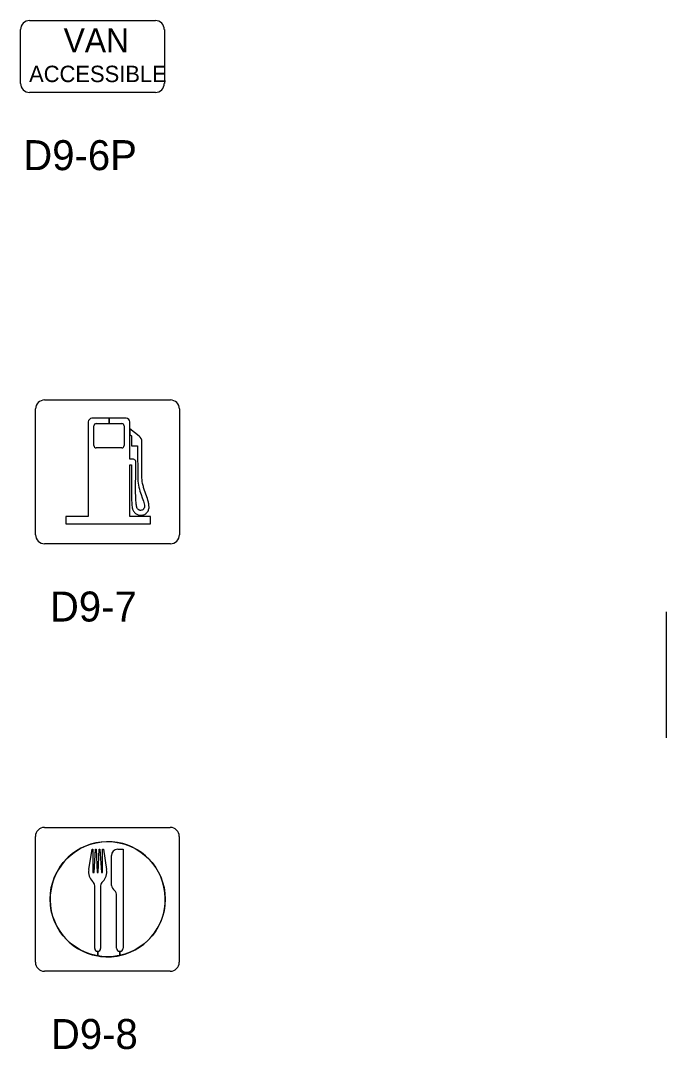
# Model space of a CAD drawing. Extents: x 42133 to 45533, y 41351 to 47951.
# Drawn here: x 42524.5 to 42686.1, y 47420.5 to 47677.8 of the extents above; entities that cross this region are included whole.
import ezdxf

# ---------------------------------------------------------------- set-up
doc = ezdxf.new("R2010")
doc.units = 0
doc.layers.add('P_TRAF_SIGN_SignDetails', color=7, linetype='Continuous')

msp = doc.modelspace()

# ---------------------------------------------------------------- linework, layer by layer
at = {"layer": 'P_TRAF_SIGN_SignDetails'}
for p, q in [((42526.75, 47677.76), (42558.23, 47677.76)), ((42524.5, 47662.03), (42524.5, 47675.51)), ((42560.48, 47675.51), (42560.48, 47662.03)), ((42558.23, 47659.79), (42526.75, 47659.79)), ((42530.52, 47582.89), (42562, 47582.89)), ((42528.26, 47549.15), (42528.26, 47580.64)), ((42564.24, 47580.64), (42564.24, 47549.15)), ((42562, 47546.91), (42530.52, 47546.91)), ((42686.09, 47498.42), (42686.09, 47529.91)), ((42530.48, 47475.99), (42561.96, 47475.99)), ((42528.23, 47442.25), (42528.23, 47473.74)), ((42564.21, 47473.74), (42564.21, 47442.25)), ((42561.96, 47440.01), (42530.48, 47440.01))]:
    msp.add_line(p, q, dxfattribs=at)
for points in [[(42541.44, 47577.37), (42541.44, 47553.76), (42535.82, 47553.76), (42535.82, 47551.9), (42557, 47551.9), (42557, 47553.76), (42551.86, 47553.76), (42551.86, 47566.63), (42552.28, 47566.63), (42552.26, 47564.41), (42552.24, 47562.81), (42552.24, 47561.08), (42552.24, 47560.21), (42552.25, 47559.36), (42552.26, 47558.55), (42552.28, 47557.8), (42552.32, 47557.12), (42552.36, 47556.53), (42552.42, 47556.05), (42552.45, 47555.86), (42552.48, 47555.71), (42552.54, 47555.53), (42552.61, 47555.37), (42552.69, 47555.2), (42552.79, 47555.05), (42552.89, 47554.91), (42553.01, 47554.76), (42553.27, 47554.52), (42553.42, 47554.41), (42553.57, 47554.31), (42553.73, 47554.23), (42553.89, 47554.16), (42554.06, 47554.1), (42554.23, 47554.06), (42554.4, 47554.03), (42554.59, 47554.03), (42554.79, 47554.03), (42554.99, 47554.07), (42555.19, 47554.12), (42555.38, 47554.19), (42555.56, 47554.27), (42555.73, 47554.38), (42555.81, 47554.43), (42555.89, 47554.5), (42556.04, 47554.63), (42556.17, 47554.78), (42556.29, 47554.94), (42556.4, 47555.11), (42556.48, 47555.29), (42556.55, 47555.48), (42556.6, 47555.68), (42556.64, 47555.88), (42556.64, 47556.09), (42556.62, 47556.51), (42556.57, 47556.94), (42556.53, 47557.15), (42556.48, 47557.36), (42556.37, 47557.8), (42556.23, 47558.23), (42556.09, 47558.67), (42555.76, 47559.56), (42555.44, 47560.49), (42555.29, 47560.98), (42555.22, 47561.22), (42555.15, 47561.47), (42555.04, 47561.98), (42554.95, 47562.49), (42554.9, 47563.03), (42554.88, 47563.3), (42554.88, 47563.58), (42554.88, 47572.47)], [(42541.44, 47577.37), (42541.44, 47553.76), (42535.82, 47553.76), (42535.82, 47551.9), (42557, 47551.9), (42557, 47553.76), (42551.86, 47553.76), (42551.86, 47566.63), (42552.28, 47566.63), (42552.26, 47564.41), (42552.24, 47562.81), (42552.24, 47561.08), (42552.24, 47560.21), (42552.25, 47559.36), (42552.26, 47558.55), (42552.28, 47557.8), (42552.32, 47557.12), (42552.36, 47556.53), (42552.42, 47556.05), (42552.45, 47555.86), (42552.48, 47555.71), (42552.54, 47555.53), (42552.61, 47555.37), (42552.69, 47555.2), (42552.79, 47555.05), (42552.89, 47554.91), (42553.01, 47554.76), (42553.27, 47554.52), (42553.42, 47554.41), (42553.57, 47554.31), (42553.73, 47554.23), (42553.89, 47554.16), (42554.06, 47554.1), (42554.23, 47554.06), (42554.4, 47554.03), (42554.59, 47554.03), (42554.79, 47554.03), (42554.99, 47554.07), (42555.19, 47554.12), (42555.38, 47554.19), (42555.56, 47554.27), (42555.73, 47554.38), (42555.81, 47554.43), (42555.89, 47554.5), (42556.04, 47554.63), (42556.17, 47554.78), (42556.29, 47554.94), (42556.4, 47555.11), (42556.48, 47555.29), (42556.55, 47555.48), (42556.6, 47555.68), (42556.64, 47555.88), (42556.64, 47556.09), (42556.62, 47556.51), (42556.57, 47556.94), (42556.53, 47557.15), (42556.48, 47557.36), (42556.37, 47557.8), (42556.23, 47558.23), (42556.09, 47558.67), (42555.76, 47559.56), (42555.44, 47560.49), (42555.29, 47560.98), (42555.22, 47561.22), (42555.15, 47561.47), (42555.04, 47561.98), (42554.95, 47562.49), (42554.9, 47563.03), (42554.88, 47563.3), (42554.88, 47563.58), (42554.88, 47572.47)], [(42541.44, 47577.37), (42541.44, 47553.76), (42535.82, 47553.76), (42535.82, 47551.9), (42557, 47551.9), (42557, 47553.76), (42551.86, 47553.76), (42551.86, 47566.63), (42552.28, 47566.63), (42552.26, 47564.41), (42552.24, 47562.81), (42552.24, 47561.08), (42552.24, 47560.21), (42552.25, 47559.36), (42552.26, 47558.55), (42552.28, 47557.8), (42552.32, 47557.12), (42552.36, 47556.53), (42552.42, 47556.05), (42552.45, 47555.86), (42552.48, 47555.71), (42552.54, 47555.53), (42552.61, 47555.37), (42552.69, 47555.2), (42552.79, 47555.05), (42552.89, 47554.91), (42553.01, 47554.76), (42553.27, 47554.52), (42553.42, 47554.41), (42553.57, 47554.31), (42553.73, 47554.23), (42553.89, 47554.16), (42554.06, 47554.1), (42554.23, 47554.06), (42554.4, 47554.03), (42554.59, 47554.03), (42554.79, 47554.03), (42554.99, 47554.07), (42555.19, 47554.12), (42555.38, 47554.19), (42555.56, 47554.27), (42555.73, 47554.38), (42555.81, 47554.43), (42555.89, 47554.5), (42556.04, 47554.63), (42556.17, 47554.78), (42556.29, 47554.94), (42556.4, 47555.11), (42556.48, 47555.29), (42556.55, 47555.48), (42556.6, 47555.68), (42556.64, 47555.88), (42556.64, 47556.09), (42556.62, 47556.51), (42556.57, 47556.94), (42556.53, 47557.15), (42556.48, 47557.36), (42556.37, 47557.8), (42556.23, 47558.23), (42556.09, 47558.67), (42555.76, 47559.56), (42555.44, 47560.49), (42555.29, 47560.98), (42555.22, 47561.22), (42555.15, 47561.47), (42555.04, 47561.98), (42554.95, 47562.49), (42554.9, 47563.03), (42554.88, 47563.3), (42554.88, 47563.58), (42554.88, 47572.47)], [(42550.93, 47578.3), (42542.37, 47578.3)], [(42543.45, 47576.96), (42546.65, 47576.96), (42546.65, 47578.3), (42542.37, 47578.3)], [(42543.45, 47576.96), (42546.65, 47576.96), (42546.65, 47578.3), (42542.37, 47578.3)], [(42542.85, 47571.49), (42542.85, 47576.37)], [(42542.85, 47571.49), (42542.85, 47576.37)], [(42542.85, 47571.49), (42542.85, 47576.37)], [(42543.45, 47576.96), (42549.83, 47576.96)], [(42550.93, 47578.3), (42546.65, 47578.3), (42546.65, 47576.96), (42549.83, 47576.96)], [(42550.93, 47578.3), (42546.65, 47578.3), (42546.65, 47576.96), (42549.83, 47576.96)], [(42550.42, 47576.37), (42550.42, 47571.49)], [(42550.42, 47576.37), (42550.42, 47571.49)], [(42550.42, 47576.37), (42550.42, 47571.49)], [(42554.15, 47573.82), (42551.86, 47575.7), (42551.86, 47577.37)], [(42554.15, 47573.82), (42551.86, 47575.7), (42551.86, 47574.23), (42552.28, 47573.91), (42552.28, 47571.45), (42553.78, 47571.45), (42553.85, 47563.07), (42553.85, 47562.82), (42553.87, 47562.56), (42553.92, 47562.05), (42554, 47561.55), (42554.11, 47561.06), (42554.22, 47560.58), (42554.36, 47560.11), (42554.66, 47559.21), (42554.96, 47558.37), (42555.1, 47557.97), (42555.22, 47557.59), (42555.33, 47557.22), (42555.41, 47556.88), (42555.47, 47556.55), (42555.49, 47556.39), (42555.5, 47556.24), (42555.48, 47556.04), (42555.43, 47555.86), (42555.39, 47555.78), (42555.34, 47555.7), (42555.28, 47555.62), (42555.22, 47555.55), (42555.15, 47555.49), (42555.08, 47555.44), (42554.91, 47555.35), (42554.82, 47555.31), (42554.73, 47555.29), (42554.53, 47555.27), (42554.42, 47555.27), (42554.31, 47555.29), (42554.2, 47555.33), (42554.08, 47555.38), (42553.97, 47555.46), (42553.86, 47555.55), (42553.76, 47555.66), (42553.67, 47555.79), (42553.61, 47555.92), (42553.56, 47556.08), (42553.51, 47556.29), (42553.47, 47556.54), (42553.43, 47556.81), (42553.4, 47557.13), (42553.35, 47557.84), (42553.31, 47558.65), (42553.3, 47559.08), (42553.29, 47559.53), (42553.28, 47560.46), (42553.28, 47561.41), (42553.29, 47562.38), (42553.3, 47563.31), (42553.33, 47565.05), (42553.36, 47566.42), (42553.37, 47567.28), (42553.36, 47567.43), (42553.31, 47567.58), (42553.24, 47567.72), (42553.14, 47567.83), (42553.03, 47567.93), (42552.9, 47568), (42552.75, 47568.05), (42552.59, 47568.06), (42551.86, 47568.09), (42551.86, 47577.37)], [(42554.15, 47573.82), (42551.86, 47575.7), (42551.86, 47574.23), (42552.28, 47573.91), (42552.28, 47571.45), (42553.78, 47571.45), (42553.85, 47563.07), (42553.85, 47562.82), (42553.87, 47562.56), (42553.92, 47562.05), (42554, 47561.55), (42554.11, 47561.06), (42554.22, 47560.58), (42554.36, 47560.11), (42554.66, 47559.21), (42554.96, 47558.37), (42555.1, 47557.97), (42555.22, 47557.59), (42555.33, 47557.22), (42555.41, 47556.88), (42555.47, 47556.55), (42555.49, 47556.39), (42555.5, 47556.24), (42555.48, 47556.04), (42555.43, 47555.86), (42555.39, 47555.78), (42555.34, 47555.7), (42555.28, 47555.62), (42555.22, 47555.55), (42555.15, 47555.49), (42555.08, 47555.44), (42554.91, 47555.35), (42554.82, 47555.31), (42554.73, 47555.29), (42554.53, 47555.27), (42554.42, 47555.27), (42554.31, 47555.29), (42554.2, 47555.33), (42554.08, 47555.38), (42553.97, 47555.46), (42553.86, 47555.55), (42553.76, 47555.66), (42553.67, 47555.79), (42553.61, 47555.92), (42553.56, 47556.08), (42553.51, 47556.29), (42553.47, 47556.54), (42553.43, 47556.81), (42553.4, 47557.13), (42553.35, 47557.84), (42553.31, 47558.65), (42553.3, 47559.08), (42553.29, 47559.53), (42553.28, 47560.46), (42553.28, 47561.41), (42553.29, 47562.38), (42553.3, 47563.31), (42553.33, 47565.05), (42553.36, 47566.42), (42553.37, 47567.28), (42553.36, 47567.43), (42553.31, 47567.58), (42553.24, 47567.72), (42553.14, 47567.83), (42553.03, 47567.93), (42552.9, 47568), (42552.75, 47568.05), (42552.59, 47568.06), (42551.86, 47568.09), (42551.86, 47577.37)], [(42549.83, 47570.89), (42543.45, 47570.89)], [(42549.83, 47570.89), (42543.45, 47570.89)], [(42549.83, 47570.89), (42543.45, 47570.89)], [(42541.57, 47465.42), (42542.39, 47470.51), (42542.57, 47470.51), (42542.57, 47464.75), (42542.88, 47464.75), (42543.27, 47470.51), (42543.4, 47470.51)], [(42541.57, 47465.42), (42542.39, 47470.51), (42542.57, 47470.51), (42542.57, 47464.75), (42542.88, 47464.75), (42543.27, 47470.51), (42543.4, 47470.51), (42543.65, 47464.75), (42543.94, 47464.75), (42544.2, 47470.51), (42544.32, 47470.51), (42544.72, 47464.75), (42545.03, 47464.75), (42545.03, 47470.51), (42545.21, 47470.51)], [(42541.57, 47465.42), (42542.39, 47470.51), (42542.57, 47470.51), (42542.57, 47464.75), (42542.88, 47464.75), (42543.27, 47470.51), (42543.4, 47470.51), (42543.65, 47464.75), (42543.94, 47464.75), (42544.2, 47470.51), (42544.32, 47470.51), (42544.72, 47464.75), (42545.03, 47464.75), (42545.03, 47470.51), (42545.21, 47470.51)], [(42543.4, 47470.51), (42543.65, 47464.75), (42543.94, 47464.75), (42544.2, 47470.51), (42544.32, 47470.51), (42544.72, 47464.75), (42545.03, 47464.75), (42545.03, 47470.51), (42545.21, 47470.51), (42546.03, 47465.42)], [(42545.21, 47470.51), (42546.03, 47465.42)], [(42545.21, 47470.51), (42546.03, 47465.42)], [(42548.83, 47470.51), (42550.14, 47470.51), (42550.14, 47445.8)], [(42548.83, 47470.51), (42550.14, 47470.51), (42550.14, 47445.8)], [(42548.83, 47470.51), (42550.14, 47470.51), (42550.14, 47445.8)], [(42547.24, 47461.47), (42547.24, 47468.92)], [(42547.24, 47461.47), (42547.24, 47468.92)], [(42547.24, 47461.47), (42547.24, 47468.92)], [(42543.06, 47445.73), (42543.06, 47461.37)], [(42543.06, 47445.73), (42543.06, 47461.37)], [(42543.06, 47445.73), (42543.06, 47461.37)], [(42544.53, 47461.37), (42544.53, 47445.73)], [(42544.53, 47461.37), (42544.53, 47445.73)], [(42544.53, 47461.37), (42544.53, 47445.73)], [(42548.53, 47445.8), (42548.53, 47458.96)], [(42548.53, 47445.8), (42548.53, 47458.96)], [(42548.53, 47445.8), (42548.53, 47458.96)], [(42543.8, 47445), (42543.8, 47443.84)], [(42543.8, 47443.84), (42543.8, 47445)], [(42543.8, 47445), (42543.8, 47443.84)], [(42543.8, 47443.84), (42543.8, 47445)], [(42549.33, 47443.94), (42549.33, 47445)], [(42549.33, 47445), (42549.33, 47443.94)], [(42549.33, 47443.94), (42549.33, 47445)], [(42549.33, 47445), (42549.33, 47443.94)]]:
    msp.add_lwpolyline(points, dxfattribs=at)
msp.add_lwpolyline([(42553.37, 47567.28), (42553.36, 47567.43), (42553.31, 47567.58), (42553.24, 47567.72), (42553.14, 47567.83), (42553.03, 47567.93), (42552.9, 47568), (42552.75, 47568.05), (42552.59, 47568.06), (42551.86, 47568.09), (42551.86, 47568.09), (42551.86, 47574.23), (42552.28, 47573.91), (42552.28, 47571.45), (42553.78, 47571.45), (42553.78, 47571.45), (42553.85, 47563.07), (42553.85, 47562.82), (42553.87, 47562.56), (42553.92, 47562.05), (42554, 47561.55), (42554.11, 47561.06), (42554.22, 47560.58), (42554.36, 47560.11), (42554.66, 47559.21), (42554.96, 47558.37), (42555.1, 47557.97), (42555.22, 47557.59), (42555.33, 47557.22), (42555.41, 47556.88), (42555.47, 47556.55), (42555.49, 47556.39), (42555.5, 47556.24), (42555.48, 47556.04), (42555.43, 47555.86), (42555.39, 47555.78), (42555.34, 47555.7), (42555.28, 47555.62), (42555.22, 47555.55), (42555.15, 47555.49), (42555.08, 47555.44), (42554.91, 47555.35), (42554.82, 47555.31), (42554.73, 47555.29), (42554.53, 47555.27), (42554.42, 47555.27), (42554.31, 47555.29), (42554.2, 47555.33), (42554.08, 47555.38), (42553.97, 47555.46), (42553.86, 47555.55), (42553.76, 47555.66), (42553.67, 47555.79), (42553.61, 47555.92), (42553.56, 47556.08), (42553.51, 47556.29), (42553.47, 47556.54), (42553.43, 47556.81), (42553.4, 47557.13), (42553.35, 47557.84), (42553.31, 47558.65), (42553.3, 47559.08), (42553.29, 47559.53), (42553.28, 47560.46), (42553.28, 47561.41), (42553.29, 47562.38), (42553.3, 47563.31), (42553.33, 47565.05), (42553.36, 47566.42)], close=True, dxfattribs=at)
msp.add_circle((42546.3, 47458.02), 14.4, dxfattribs=at)
for centre, radius, start, end in [((42526.75, 47675.51), 2.24, 90, 180), ((42558.23, 47675.51), 2.24, 0, 90), ((42526.75, 47662.03), 2.24, 180, 270), ((42558.23, 47662.03), 2.24, 270, 360), ((42530.51, 47580.64), 2.24, 90, 180), ((42562, 47580.64), 2.24, 0, 90), ((42542.37, 47577.37), 0.924, 90, 180), ((42542.37, 47577.37), 0.924, 90, 180), ((42542.37, 47577.37), 0.924, 90, 180), ((42543.45, 47576.37), 0.594, 90, 180), ((42543.45, 47576.37), 0.594, 90, 180), ((42543.45, 47576.37), 0.594, 90, 180), ((42549.83, 47576.37), 0.594, 360, 90), ((42549.83, 47576.37), 0.594, 360, 90), ((42549.83, 47576.37), 0.594, 360, 90), ((42550.93, 47577.37), 0.924, 0, 90), ((42550.93, 47577.37), 0.924, 0, 90), ((42550.93, 47577.37), 0.924, 0, 90), ((42553.05, 47572.36), 1.83, 3.333, 53.2359), ((42553.05, 47572.36), 1.83, 3.333, 53.2359), ((42553.05, 47572.36), 1.83, 3.333, 53.2359), ((42543.45, 47571.49), 0.594, 180, 270), ((42543.45, 47571.49), 0.594, 180, 270), ((42543.45, 47571.49), 0.594, 180, 270), ((42549.83, 47571.49), 0.594, 270, 0), ((42549.83, 47571.49), 0.594, 270, 0), ((42549.83, 47571.49), 0.594, 270, 0), ((42530.51, 47549.16), 2.24, 180, 270), ((42562, 47549.16), 2.24, 270, 0), ((42530.47, 47473.74), 2.24, 90, 180), ((42561.96, 47473.74), 2.24, 0, 90), ((42546.3, 47458.02), 14.4, 282.1473, 259.9688), ((42546.3, 47458.02), 14.4, 282.1473, 259.9688), ((42548.83, 47468.92), 1.59, 90, 180), ((42548.83, 47468.92), 1.59, 90, 180), ((42548.83, 47468.92), 1.59, 90, 180), ((42544.81, 47464.8), 3.3, 169.2197, 225.2196), ((42544.81, 47464.8), 3.3, 169.2197, 225.2196), ((42544.81, 47464.8), 3.3, 169.2197, 225.2196), ((42542.78, 47464.8), 3.3, 314.7804, 10.7803), ((42542.78, 47464.8), 3.3, 314.7804, 10.7803), ((42542.78, 47464.8), 3.3, 314.7804, 10.7803), ((42541.85, 47461.42), 1.21, 357.6425, 58.5927), ((42541.85, 47461.42), 1.21, 357.6425, 58.5927), ((42541.85, 47461.42), 1.21, 357.6425, 58.5927), ((42545.74, 47461.42), 1.21, 121.4073, 182.3575), ((42545.74, 47461.42), 1.21, 121.4073, 182.3575), ((42545.74, 47461.42), 1.21, 121.4073, 182.3575), ((42549.88, 47462.14), 2.72, 194.2432, 226.1822), ((42549.88, 47462.14), 2.72, 194.2432, 226.1822), ((42549.88, 47462.14), 2.72, 194.2432, 226.1822), ((42546.9, 47458.96), 1.64, 359.9543, 47.9869), ((42546.9, 47458.96), 1.64, 359.9543, 47.9869), ((42546.9, 47458.96), 1.64, 359.9543, 47.9869), ((42543.8, 47445.73), 0.734, 180, 360), ((42543.8, 47445.73), 0.734, 180, 269.8877), ((42543.8, 47445.73), 0.734, 180, 269.8877), ((42543.8, 47445.73), 0.734, 270, 0), ((42543.8, 47445.73), 0.734, 270, 0), ((42549.33, 47445.8), 0.802, 180, 360), ((42549.33, 47445.8), 0.802, 180, 269.8971), ((42549.33, 47445.8), 0.802, 180, 269.8971), ((42549.33, 47445.8), 0.802, 270, 0), ((42549.33, 47445.8), 0.802, 270, 0), ((42530.47, 47442.26), 2.24, 180, 270), ((42546.3, 47458.02), 14.4, 259.9746, 282.1414), ((42546.3, 47458.02), 14.4, 259.9746, 282.1414), ((42561.96, 47442.26), 2.24, 270, 0)]:
    msp.add_arc(centre, radius, start, end, dxfattribs=at)

# ---------------------------------------------------------------- texts
for s, height, p in [('VAN', 5.945, (42535.28, 47669.85)), ('ACCESSIBLE', 4.102, (42526.63, 47662.37)), ('D9-6P', 7.5, (42525.18, 47640.35)), ('D9-7', 7.5, (42531.84, 47527.47)), ('D9-8', 7.5, (42532.09, 47420.57))]:
    msp.add_text(s, height=height, dxfattribs=at).set_placement(p)

doc.saveas('drawing.dxf')
